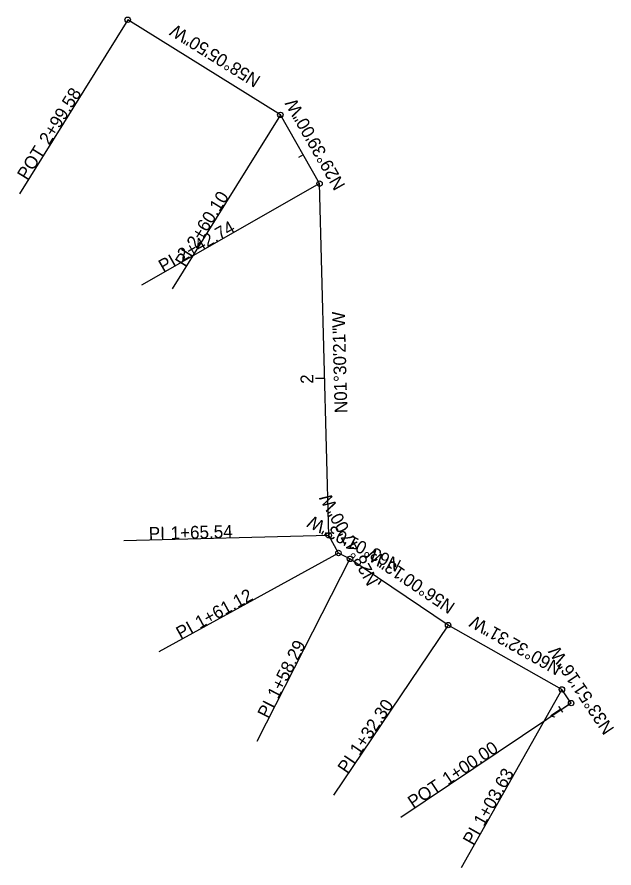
# Model space of a CAD drawing. Extents: x 2274565 to 2274696, y 654596 to 654783.
import ezdxf

# ---------------------------------------------------------------- set-up
doc = ezdxf.new("R2010")
doc.units = 0
for name, color, linetype in [('DR_P_Flow_Arrow', 7, 'Continuous'), ('DR_X_Culvert', 7, 'Continuous'), ('DR_X_Culvert3D', 7, 'Continuous'), ('PF_X_Ground_Line', 7, 'Continuous'), ('SC_Scratch12', 7, 'Continuous'), ('SC_Scratch6', 7, 'Continuous'), ('SC_Scratch7', 7, 'Continuous')]:
    doc.layers.add(name, color=color, linetype=linetype)

msp = doc.modelspace()

# ---------------------------------------------------------------- linework, layer by layer
at = {"layer": 'DR_X_Culvert'}
for p, q in [((2274589.53, 654782.32), (2274565.75, 654744.12)), ((2274623.04, 654761.45), (2274599.26, 654723.25)), ((2274631.63, 654746.37), (2274592.53, 654724.1)), ((2274632.76, 654703.64), (2274631.56, 654703.61)), ((2274633.66, 654669.2), (2274588.68, 654668.02)), ((2274635.79, 654665.32), (2274596.35, 654643.65)), ((2274638.31, 654664.04), (2274617.89, 654623.94)), ((2274659.86, 654649.51), (2274634.7, 654612.2)), ((2274684.82, 654635.4), (2274662.69, 654596.22)), ((2274686.85, 654632.39), (2274649.48, 654607.32)), ((2274686.85, 654632.39), (2274685.85, 654631.72))]:
    msp.add_line(p, q, dxfattribs=at)
for centre in [(2274589.53, 654782.32), (2274623.04, 654761.45), (2274631.63, 654746.37), (2274633.66, 654669.2), (2274635.79, 654665.32), (2274638.31, 654664.04), (2274659.86, 654649.51), (2274684.82, 654635.4), (2274686.85, 654632.39)]:
    msp.add_circle(centre, 0.6, dxfattribs=at)
at = {"layer": 'SC_Scratch12'}
for p, q in [((2274589.53, 654782.32), (2274565.75, 654744.12)), ((2274623.04, 654761.45), (2274599.26, 654723.25)), ((2274628.04, 654752.68), (2274627, 654752.08)), ((2274631.63, 654746.37), (2274592.53, 654724.1)), ((2274632.76, 654703.64), (2274630.76, 654703.59)), ((2274633.66, 654669.2), (2274588.68, 654668.02)), ((2274635.79, 654665.32), (2274596.35, 654643.65)), ((2274638.31, 654664.04), (2274617.89, 654623.94)), ((2274645.19, 654659.4), (2274644.51, 654658.41)), ((2274659.86, 654649.51), (2274634.7, 654612.2)), ((2274684.82, 654635.4), (2274662.69, 654596.22)), ((2274686.85, 654632.39), (2274649.48, 654607.32)), ((2274686.85, 654632.39), (2274685.18, 654631.28))]:
    msp.add_line(p, q, dxfattribs=at)
for centre in [(2274589.53, 654782.32), (2274623.04, 654761.45), (2274631.63, 654746.37), (2274633.66, 654669.2), (2274635.79, 654665.32), (2274638.31, 654664.04), (2274659.86, 654649.51), (2274684.82, 654635.4), (2274686.85, 654632.39)]:
    msp.add_circle(centre, 0.6, dxfattribs=at)
at = {"layer": 'SC_Scratch6'}
for p, q in [((2274589.53, 654782.32), (2274565.75, 654744.12)), ((2274623.04, 654761.45), (2274599.26, 654723.25)), ((2274631.63, 654746.37), (2274592.53, 654724.1)), ((2274633.66, 654669.2), (2274588.68, 654668.02)), ((2274635.79, 654665.32), (2274596.35, 654643.65)), ((2274638.31, 654664.04), (2274617.89, 654623.94)), ((2274659.86, 654649.51), (2274634.7, 654612.2)), ((2274684.82, 654635.4), (2274662.69, 654596.22)), ((2274686.85, 654632.39), (2274649.48, 654607.32))]:
    msp.add_line(p, q, dxfattribs=at)
for centre in [(2274589.53, 654782.32), (2274623.04, 654761.45), (2274631.63, 654746.37), (2274633.66, 654669.2), (2274635.79, 654665.32), (2274638.31, 654664.04), (2274659.86, 654649.51), (2274684.82, 654635.4), (2274686.85, 654632.39)]:
    msp.add_circle(centre, 0.6, dxfattribs=at)
at = {"layer": 'SC_Scratch7'}
for p, q in [((2274623.04, 654761.45), (2274589.53, 654782.32)), ((2274631.63, 654746.37), (2274623.04, 654761.45)), ((2274633.66, 654669.2), (2274631.63, 654746.37)), ((2274635.79, 654665.32), (2274633.66, 654669.2)), ((2274638.31, 654664.04), (2274635.79, 654665.32)), ((2274659.86, 654649.51), (2274638.31, 654664.04)), ((2274684.82, 654635.4), (2274659.86, 654649.51)), ((2274686.85, 654632.39), (2274684.82, 654635.4))]:
    msp.add_line(p, q, dxfattribs=at)

# ---------------------------------------------------------------- texts
at = {"layer": 'DR_P_Flow_Arrow'}
for s, rotation, p in [('N58°05\'50"W', 148.0971, (2274618.9, 654769.69)), ('N29°39\'00"W', 119.65, (2274637.38, 654745.97)), ('N01°30\'21"W', 91.5059, (2274637.76, 654696.05)), ('N28°47\'00"W', 118.7833, (2274644.65, 654659.17)), ('N63°01\'03"W', 153.0175, (2274649.8, 654663.57)), ('N56°00\'13"W', 146.0036, (2274661.6, 654654.12)), ('N60°32\'31"W', 150.5419, (2274685.03, 654640.8)), ('N33°51\'16"W', 123.8544, (2274696.43, 654626.72))]:
    msp.add_text(s, height=2.8, rotation=rotation, dxfattribs=at).set_placement(p)
at = {"layer": 'DR_X_Culvert'}
for s, rotation, p in [('2+99.58', 58.0971, (2274572.27, 654754.69)), ('POT', 58.0971, (2274567.45, 654746.94)), ('2+60.10', 58.0971, (2274604.64, 654731.98)), ('2+42.74', 29.65, (2274601.47, 654729.2)), ('PI', 29.65, (2274597.32, 654726.83)), ('PI', 58.0971, (2274602.11, 654727.92)), ('PI', 1.5059, (2274594.19, 654668.21)), ('1+65.54', 1.5059, (2274598.97, 654668.33)), ('1+61.12', 28.7833, (2274605.32, 654648.63)), ('PI', 28.7833, (2274601.13, 654646.33)), ('1+58.29', 63.0175, (2274622.52, 654633.12)), ('PI', 63.0175, (2274620.35, 654628.86)), ('1+32.30', 56.0036, (2274640.39, 654620.72)), ('1+00.00', 33.8544, (2274659.77, 654614.28)), ('PI', 56.0036, (2274637.71, 654616.76)), ('1+03.63', 60.5419, (2274667.7, 654605.19)), ('POT', 33.8544, (2274652.19, 654609.2)), ('PI', 60.5419, (2274665.35, 654601.02))]:
    msp.add_text(s, height=2.8, rotation=rotation, dxfattribs=at).set_placement(p)
at = {"layer": 'DR_X_Culvert3D'}
for s, rotation, p in [('N58°05\'50"W', 148.0971, (2274618.9, 654769.69)), ('N29°39\'00"W', 119.65, (2274637.38, 654745.97)), ('N01°30\'21"W', 91.5059, (2274637.76, 654696.05)), ('N28°47\'00"W', 118.7833, (2274644.65, 654659.17)), ('N63°01\'03"W', 153.0175, (2274649.8, 654663.57)), ('N56°00\'13"W', 146.0036, (2274661.6, 654654.12)), ('N60°32\'31"W', 150.5419, (2274685.03, 654640.8)), ('N33°51\'16"W', 123.8544, (2274696.43, 654626.72))]:
    msp.add_text(s, height=2.8, rotation=rotation, dxfattribs=at).set_placement(p)
at = {"layer": 'PF_X_Ground_Line'}
for s, rotation, p in [('N58°05\'50"W', 148.0971, (2274618.9, 654769.69)), ('N29°39\'00"W', 119.65, (2274637.38, 654745.97)), ('N01°30\'21"W', 91.5059, (2274637.76, 654696.05)), ('N28°47\'00"W', 118.7833, (2274644.65, 654659.17)), ('N63°01\'03"W', 153.0175, (2274649.8, 654663.57)), ('N56°00\'13"W', 146.0036, (2274661.6, 654654.12)), ('N60°32\'31"W', 150.5419, (2274685.03, 654640.8)), ('N33°51\'16"W', 123.8544, (2274696.43, 654626.72))]:
    msp.add_text(s, height=2.8, rotation=rotation, dxfattribs=at).set_placement(p)
at = {"layer": 'SC_Scratch12'}
for s, rotation, p in [('2+99.58', 58.0971, (2274572.27, 654754.69)), ('POT', 58.0971, (2274567.45, 654746.94)), ('2+60.10', 58.0971, (2274604.64, 654731.98)), ('2+42.74', 29.65, (2274601.47, 654729.2)), ('PI', 29.65, (2274597.32, 654726.83)), ('PI', 58.0971, (2274602.11, 654727.92)), ('2', 91.5059, (2274630.29, 654702.48)), ('PI', 1.5059, (2274594.19, 654668.21)), ('1+65.54', 1.5059, (2274598.97, 654668.33)), ('1+61.12', 28.7833, (2274605.32, 654648.63)), ('PI', 28.7833, (2274601.13, 654646.33)), ('1+58.29', 63.0175, (2274622.52, 654633.12)), ('PI', 63.0175, (2274620.35, 654628.86)), ('1+32.30', 56.0036, (2274640.39, 654620.72)), ('1', 123.8544, (2274685.29, 654630.22)), ('1+00.00', 33.8544, (2274659.77, 654614.28)), ('PI', 56.0036, (2274637.71, 654616.76)), ('1+03.63', 60.5419, (2274667.7, 654605.19)), ('POT', 33.8544, (2274652.19, 654609.2)), ('PI', 60.5419, (2274665.35, 654601.02))]:
    msp.add_text(s, height=2.8, rotation=rotation, dxfattribs=at).set_placement(p)
at = {"layer": 'SC_Scratch6'}
for s, rotation, p in [('2+99.58', 58.0971, (2274572.27, 654754.69)), ('POT', 58.0971, (2274567.45, 654746.94)), ('2+60.10', 58.0971, (2274604.64, 654731.98)), ('2+42.74', 29.65, (2274601.47, 654729.2)), ('PI', 29.65, (2274597.32, 654726.83)), ('PI', 58.0971, (2274602.11, 654727.92)), ('PI', 1.5059, (2274594.19, 654668.21)), ('1+65.54', 1.5059, (2274598.97, 654668.33)), ('1+61.12', 28.7833, (2274605.32, 654648.63)), ('PI', 28.7833, (2274601.13, 654646.33)), ('1+58.29', 63.0175, (2274622.52, 654633.12)), ('PI', 63.0175, (2274620.35, 654628.86)), ('1+32.30', 56.0036, (2274640.39, 654620.72)), ('1+00.00', 33.8544, (2274659.77, 654614.28)), ('PI', 56.0036, (2274637.71, 654616.76)), ('1+03.63', 60.5419, (2274667.7, 654605.19)), ('POT', 33.8544, (2274652.19, 654609.2)), ('PI', 60.5419, (2274665.35, 654601.02))]:
    msp.add_text(s, height=2.8, rotation=rotation, dxfattribs=at).set_placement(p)

doc.saveas('drawing.dxf')
